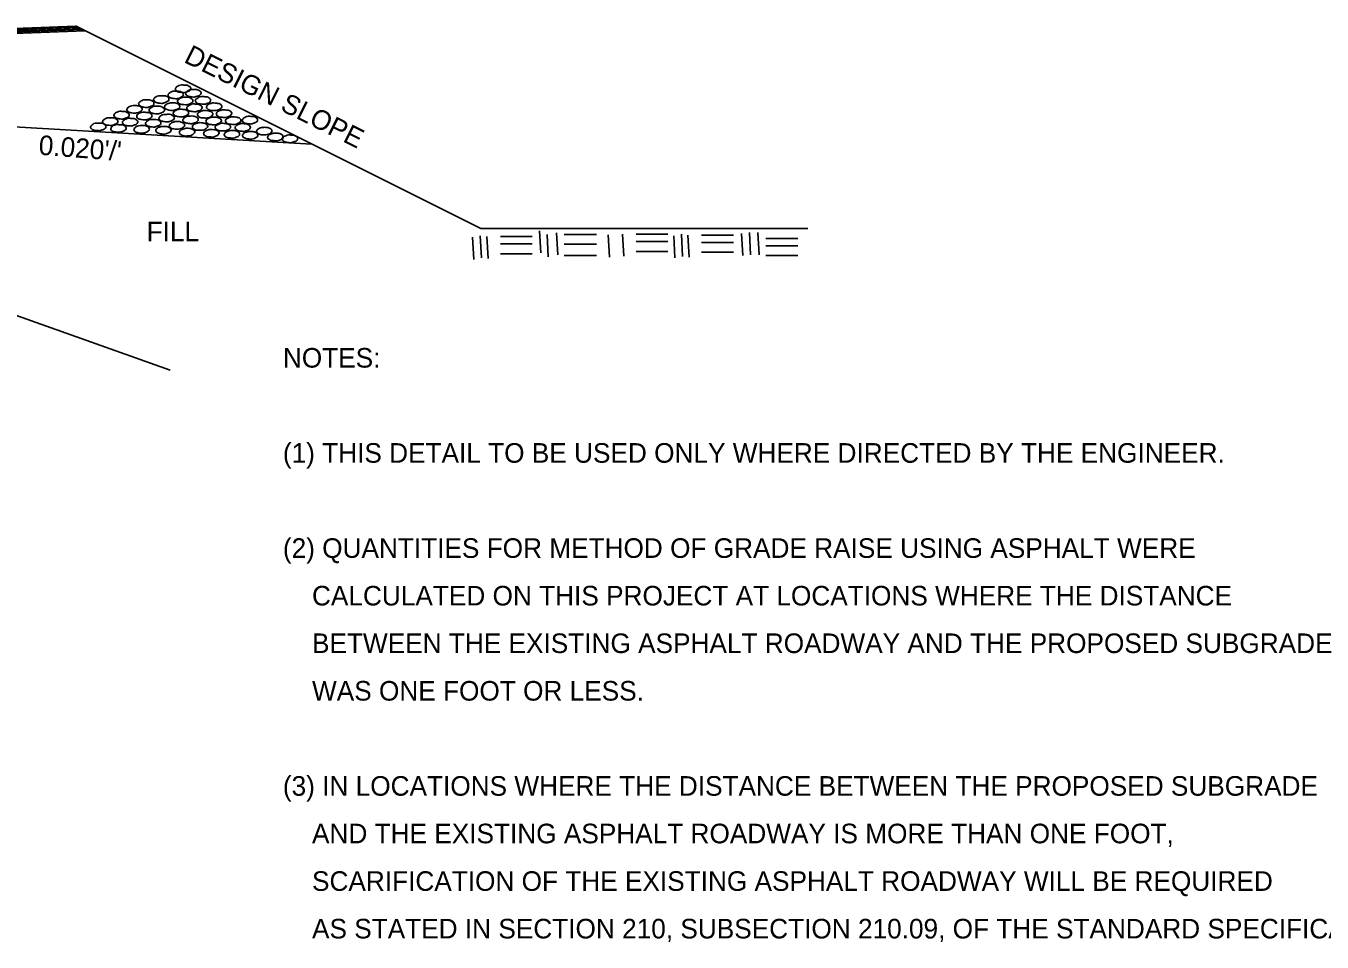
# Model space of a CAD drawing. Extents: x 3575 to 11445, y 9479 to 13278.
# Drawn here: x 5116.4 to 5513.3, y 10594.7 to 10875.3 of the extents above; entities that cross this region are included whole.
import ezdxf

# ---------------------------------------------------------------- set-up
doc = ezdxf.new("R2010")
doc.units = 0
doc.layers.add('STAMP_PE_CRAFTON-SIGNATURE', color=7, linetype='Continuous')

msp = doc.modelspace()

# ---------------------------------------------------------------- linework, layer by layer
at = {"layer": 'STAMP_PE_CRAFTON-SIGNATURE'}
for p, q in [((4487.26, 10848.04), (5134.52, 10873.86)), ((4488.11, 10848.48), (5133.79, 10874.23)), ((4488.94, 10848.88), (5133.08, 10874.59)), ((4489.79, 10849.32), (5132.33, 10874.95)), ((4490.54, 10849.68), (5131.64, 10875.29)), ((5255.72, 10813.26), (5131.53, 10875.33)), ((5050.17, 10848.13), (5203.96, 10839.12)), ((4986.73, 10831.75), (5160.57, 10769.89)), ((5355.8, 10813.26), (5255.72, 10813.26)), ((5273.69, 10812.54), (5274.04, 10805.78)), ((5253.18, 10810.59), (5253.57, 10803.82)), ((5255.51, 10811.05), (5255.9, 10804.28)), ((5257.54, 10810.83), (5257.91, 10804.06)), ((5271.47, 10810.83), (5261.68, 10810.83)), ((5271.47, 10808.57), (5261.68, 10808.57)), ((5275.98, 10811.4), (5276.35, 10804.63)), ((5278.86, 10811.99), (5279.24, 10805.21)), ((5291.1, 10811.41), (5281.27, 10811.41)), ((5291.1, 10808.51), (5281.27, 10808.51)), ((5294.72, 10811.32), (5295.12, 10804.55)), ((5299.08, 10811.57), (5299.46, 10804.8)), ((5313, 10811.57), (5303.23, 10811.57)), ((5313, 10809.31), (5303.23, 10809.31)), ((5314.76, 10811.03), (5315.15, 10804.27)), ((5317.11, 10811.51), (5317.46, 10804.73)), ((5319.12, 10811.27), (5319.5, 10804.49)), ((5333.05, 10811.27), (5323.27, 10811.27)), ((5333.05, 10809.03), (5323.27, 10809.03)), ((5335.53, 10811.75), (5335.9, 10804.99)), ((5337.96, 10812.01), (5338.33, 10805.25)), ((5340.52, 10812.01), (5340.9, 10805.25)), ((5352.81, 10810.25), (5343.02, 10810.25)), ((5271.47, 10805.56), (5261.68, 10805.56)), ((5291.1, 10805.05), (5281.27, 10805.05)), ((5313, 10806.28), (5303.23, 10806.28)), ((5333.05, 10806.01), (5323.27, 10806.01)), ((5352.81, 10808.01), (5343.02, 10808.01)), ((5352.81, 10804.97), (5343.02, 10804.97))]:
    msp.add_line(p, q, dxfattribs=at)
for points in [[(5164.52, 10854.9), (5163.68, 10855), (5162.71, 10855.25), (5162.24, 10855.74), (5162.16, 10856), (5162.41, 10856.52), (5162.64, 10856.75), (5163.21, 10857.05), (5164.01, 10857.25), (5164.43, 10857.25), (5165.06, 10857.22), (5165.75, 10857.17), (5166.27, 10856.9), (5166.8, 10856.5), (5166.88, 10856.13), (5166.73, 10855.71), (5166.34, 10855.39), (5165.96, 10855.24), (5165.4, 10855.04), (5165.06, 10854.91), (5164.52, 10854.9)], [(5167.69, 10853.54), (5166.88, 10853.65), (5165.87, 10853.88), (5165.38, 10854.38), (5165.31, 10854.63), (5165.57, 10855.16), (5165.85, 10855.36), (5166.4, 10855.68), (5167.19, 10855.9), (5167.59, 10855.9), (5168.24, 10855.83), (5168.93, 10855.8), (5169.47, 10855.53), (5169.94, 10855.12), (5170.03, 10854.77), (5169.87, 10854.37), (5169.52, 10854.02), (5169.11, 10853.86), (5168.57, 10853.67), (5168.24, 10853.57), (5167.69, 10853.54)], [(5153.28, 10850.33), (5152.46, 10850.42), (5151.46, 10850.76), (5150.99, 10851.17), (5150.9, 10851.47), (5151.16, 10851.98), (5151.44, 10852.23), (5151.96, 10852.52), (5152.75, 10852.7), (5153.19, 10852.7), (5153.81, 10852.74), (5154.5, 10852.6), (5155.05, 10852.35), (5155.54, 10851.93), (5155.61, 10851.62), (5155.49, 10851.15), (5155.09, 10850.83), (5154.74, 10850.71), (5154.14, 10850.51), (5153.81, 10850.39), (5153.28, 10850.33)], [(5157.89, 10851.62), (5157.04, 10851.71), (5156.05, 10852), (5155.54, 10852.44), (5155.49, 10852.76), (5155.74, 10853.25), (5156.02, 10853.5), (5156.56, 10853.78), (5157.37, 10853.96), (5157.79, 10853.96), (5158.42, 10853.93), (5159.12, 10853.89), (5159.62, 10853.67), (5160.11, 10853.21), (5160.19, 10852.91), (5160.03, 10852.43), (5159.65, 10852.14), (5159.28, 10851.99), (5158.75, 10851.76), (5158.42, 10851.63), (5157.89, 10851.62)], [(5162.28, 10853.03), (5161.45, 10853.13), (5160.45, 10853.4), (5159.97, 10853.86), (5159.91, 10854.15), (5160.16, 10854.64), (5160.42, 10854.88), (5160.98, 10855.19), (5161.77, 10855.39), (5162.2, 10855.39), (5162.81, 10855.32), (5163.52, 10855.28), (5164.04, 10855.08), (5164.52, 10854.61), (5164.6, 10854.33), (5164.45, 10853.84), (5164.08, 10853.57), (5163.71, 10853.37), (5163.13, 10853.15), (5162.81, 10853.05), (5162.28, 10853.03)], [(5165.23, 10851.17), (5164.36, 10851.26), (5163.38, 10851.51), (5162.88, 10852), (5162.81, 10852.27), (5163.06, 10852.79), (5163.34, 10853), (5163.9, 10853.3), (5164.7, 10853.53), (5165.12, 10853.53), (5165.75, 10853.46), (5166.44, 10853.43), (5166.95, 10853.15), (5167.45, 10852.76), (5167.53, 10852.4), (5167.37, 10851.98), (5166.98, 10851.64), (5166.63, 10851.51), (5166.09, 10851.3), (5165.75, 10851.17), (5165.23, 10851.17)], [(5170.7, 10851.34), (5169.81, 10851.43), (5168.86, 10851.64), (5168.33, 10852.16), (5168.27, 10852.41), (5168.53, 10852.94), (5168.82, 10853.15), (5169.38, 10853.48), (5170.18, 10853.68), (5170.58, 10853.68), (5171.21, 10853.65), (5171.9, 10853.6), (5172.44, 10853.33), (5172.9, 10852.92), (5172.99, 10852.58), (5172.83, 10852.14), (5172.47, 10851.81), (5172.09, 10851.64), (5171.55, 10851.47), (5171.21, 10851.35), (5170.7, 10851.34)], [(5145.69, 10846.8), (5144.85, 10846.9), (5143.88, 10847.16), (5143.41, 10847.65), (5143.33, 10847.91), (5143.57, 10848.44), (5143.8, 10848.66), (5144.37, 10848.94), (5145.18, 10849.18), (5145.59, 10849.18), (5146.2, 10849.13), (5146.91, 10849.07), (5147.43, 10848.8), (5147.96, 10848.4), (5148.03, 10848.05), (5147.89, 10847.62), (5147.49, 10847.3), (5147.14, 10847.15), (5146.56, 10846.94), (5146.2, 10846.81), (5145.69, 10846.8)], [(5149.71, 10848.6), (5148.85, 10848.69), (5147.87, 10848.96), (5147.35, 10849.4), (5147.29, 10849.7), (5147.52, 10850.2), (5147.85, 10850.44), (5148.42, 10850.79), (5149.21, 10850.94), (5149.6, 10850.94), (5150.22, 10850.91), (5150.92, 10850.83), (5151.45, 10850.63), (5151.93, 10850.16), (5151.99, 10849.88), (5151.83, 10849.39), (5151.46, 10849.11), (5151.11, 10848.92), (5150.59, 10848.75), (5150.25, 10848.66), (5149.71, 10848.6)], [(5152.7, 10846.54), (5151.83, 10846.64), (5150.87, 10846.9), (5150.39, 10847.37), (5150.32, 10847.66), (5150.57, 10848.17), (5150.81, 10848.42), (5151.39, 10848.7), (5152.17, 10848.89), (5152.59, 10848.89), (5153.23, 10848.86), (5153.92, 10848.8), (5154.44, 10848.58), (5154.95, 10848.13), (5155.02, 10847.83), (5154.86, 10847.34), (5154.5, 10847.07), (5154.11, 10846.9), (5153.55, 10846.68), (5153.23, 10846.55), (5152.7, 10846.54)], [(5156.5, 10848.38), (5155.67, 10848.48), (5154.71, 10848.75), (5154.2, 10849.23), (5154.11, 10849.47), (5154.37, 10850.03), (5154.67, 10850.25), (5155.17, 10850.58), (5155.98, 10850.76), (5156.41, 10850.76), (5157.04, 10850.78), (5157.74, 10850.66), (5158.27, 10850.39), (5158.77, 10849.99), (5158.83, 10849.67), (5158.69, 10849.21), (5158.32, 10848.87), (5157.93, 10848.71), (5157.37, 10848.55), (5157.04, 10848.44), (5156.5, 10848.38)], [(5159.53, 10845.92), (5158.69, 10846.01), (5157.72, 10846.31), (5157.22, 10846.74), (5157.14, 10847.03), (5157.4, 10847.53), (5157.69, 10847.82), (5158.2, 10848.08), (5159.01, 10848.25), (5159.42, 10848.25), (5160.04, 10848.29), (5160.74, 10848.17), (5161.28, 10847.92), (5161.78, 10847.48), (5161.86, 10847.2), (5161.71, 10846.71), (5161.33, 10846.43), (5160.95, 10846.25), (5160.39, 10846.09), (5160.04, 10845.96), (5159.53, 10845.92)], [(5161.22, 10849.42), (5160.38, 10849.52), (5159.37, 10849.82), (5158.85, 10850.25), (5158.79, 10850.56), (5159.07, 10851.04), (5159.33, 10851.3), (5159.94, 10851.6), (5160.72, 10851.79), (5161.11, 10851.79), (5161.74, 10851.76), (5162.42, 10851.68), (5162.98, 10851.48), (5163.43, 10851), (5163.52, 10850.74), (5163.36, 10850.24), (5163, 10849.98), (5162.62, 10849.78), (5162.11, 10849.6), (5161.77, 10849.48), (5161.22, 10849.42)], [(5163.88, 10847.45), (5163.05, 10847.54), (5162.07, 10847.83), (5161.58, 10848.29), (5161.52, 10848.58), (5161.77, 10849.09), (5162, 10849.31), (5162.58, 10849.6), (5163.37, 10849.82), (5163.78, 10849.82), (5164.41, 10849.78), (5165.11, 10849.72), (5165.64, 10849.45), (5166.16, 10849.04), (5166.22, 10848.71), (5166.08, 10848.25), (5165.71, 10847.96), (5165.33, 10847.82), (5164.76, 10847.58), (5164.41, 10847.47), (5163.88, 10847.45)], [(5168.02, 10849.04), (5167.18, 10849.16), (5166.19, 10849.39), (5165.71, 10849.89), (5165.63, 10850.15), (5165.88, 10850.69), (5166.17, 10850.88), (5166.73, 10851.21), (5167.52, 10851.43), (5167.93, 10851.43), (5168.55, 10851.36), (5169.25, 10851.32), (5169.77, 10851.06), (5170.28, 10850.65), (5170.35, 10850.3), (5170.2, 10849.88), (5169.81, 10849.56), (5169.45, 10849.37), (5168.88, 10849.21), (5168.55, 10849.07), (5168.02, 10849.04)], [(5171.22, 10849.44), (5172.09, 10849.35), (5173.07, 10849.09), (5173.59, 10848.61), (5173.65, 10848.33), (5173.41, 10847.84), (5173.11, 10847.6), (5172.53, 10847.28), (5171.76, 10847.1), (5171.33, 10847.1), (5170.72, 10847.15), (5170.02, 10847.18), (5169.5, 10847.41), (5169.01, 10847.87), (5168.94, 10848.17), (5169.09, 10848.63), (5169.48, 10848.92), (5169.81, 10849.11), (5170.38, 10849.31), (5170.72, 10849.4), (5171.22, 10849.44)], [(5173.99, 10851.76), (5174.81, 10851.64), (5175.8, 10851.43), (5176.33, 10850.92), (5176.4, 10850.68), (5176.16, 10850.14), (5175.87, 10849.94), (5175.28, 10849.58), (5174.5, 10849.39), (5174.09, 10849.39), (5173.48, 10849.45), (5172.76, 10849.5), (5172.23, 10849.74), (5171.77, 10850.17), (5171.71, 10850.51), (5171.86, 10850.94), (5172.19, 10851.27), (5172.56, 10851.46), (5173.11, 10851.6), (5173.46, 10851.74), (5173.99, 10851.76)], [(5177, 10849.65), (5177.85, 10849.56), (5178.83, 10849.31), (5179.36, 10848.82), (5179.42, 10848.57), (5179.17, 10848.04), (5178.89, 10847.83), (5178.3, 10847.48), (5177.54, 10847.3), (5177.1, 10847.3), (5176.47, 10847.34), (5175.75, 10847.39), (5175.26, 10847.66), (5174.77, 10848.06), (5174.71, 10848.42), (5174.87, 10848.84), (5175.22, 10849.18), (5175.58, 10849.32), (5176.15, 10849.5), (5176.46, 10849.64), (5177, 10849.65)], [(5138.52, 10843.25), (5137.69, 10843.32), (5136.73, 10843.56), (5136.25, 10844.06), (5136.16, 10844.32), (5136.43, 10844.87), (5136.67, 10845.08), (5137.23, 10845.4), (5138.04, 10845.59), (5138.43, 10845.59), (5139.08, 10845.55), (5139.78, 10845.5), (5140.32, 10845.25), (5140.79, 10844.83), (5140.88, 10844.49), (5140.72, 10844.05), (5140.38, 10843.73), (5139.95, 10843.55), (5139.41, 10843.37), (5139.08, 10843.26), (5138.52, 10843.25)], [(5142.21, 10844.87), (5141.36, 10844.92), (5140.42, 10845.21), (5139.9, 10845.67), (5139.84, 10845.96), (5140.1, 10846.47), (5140.36, 10846.7), (5140.91, 10847.01), (5141.69, 10847.2), (5142.11, 10847.2), (5142.77, 10847.17), (5143.47, 10847.13), (5143.96, 10846.87), (5144.47, 10846.44), (5144.56, 10846.12), (5144.4, 10845.66), (5144.05, 10845.37), (5143.63, 10845.19), (5143.07, 10844.96), (5142.77, 10844.87), (5142.21, 10844.87)], [(5144.77, 10842.75), (5143.9, 10842.84), (5142.92, 10843.11), (5142.44, 10843.56), (5142.35, 10843.87), (5142.65, 10844.37), (5142.86, 10844.61), (5143.47, 10844.9), (5144.24, 10845.1), (5144.64, 10845.1), (5145.28, 10845.06), (5145.97, 10845), (5146.5, 10844.78), (5147.01, 10844.32), (5147.1, 10844.02), (5146.92, 10843.54), (5146.56, 10843.27), (5146.19, 10843.09), (5145.61, 10842.87), (5145.28, 10842.77), (5144.77, 10842.75)], [(5148.3, 10844.68), (5147.45, 10844.76), (5146.5, 10845), (5146.01, 10845.5), (5145.93, 10845.76), (5146.19, 10846.29), (5146.43, 10846.5), (5147, 10846.81), (5147.81, 10847.03), (5148.19, 10847.03), (5148.83, 10846.98), (5149.52, 10846.94), (5150.06, 10846.68), (5150.57, 10846.25), (5150.65, 10845.92), (5150.49, 10845.47), (5150.11, 10845.16), (5149.74, 10844.99), (5149.2, 10844.81), (5148.83, 10844.69), (5148.3, 10844.68)], [(5151.85, 10842.46), (5151.01, 10842.56), (5150.05, 10842.82), (5149.55, 10843.3), (5149.49, 10843.55), (5149.74, 10844.1), (5149.99, 10844.3), (5150.55, 10844.63), (5151.34, 10844.83), (5151.75, 10844.83), (5152.4, 10844.79), (5153.08, 10844.74), (5153.61, 10844.48), (5154.11, 10844.06), (5154.2, 10843.72), (5154.06, 10843.28), (5153.66, 10842.95), (5153.3, 10842.81), (5152.72, 10842.61), (5152.4, 10842.47), (5151.85, 10842.46)], [(5155.46, 10844.34), (5154.59, 10844.44), (5153.59, 10844.74), (5153.08, 10845.17), (5152.99, 10845.47), (5153.27, 10845.97), (5153.55, 10846.21), (5154.12, 10846.52), (5154.91, 10846.71), (5155.33, 10846.71), (5155.94, 10846.69), (5156.65, 10846.61), (5157.18, 10846.39), (5157.65, 10845.93), (5157.74, 10845.63), (5157.57, 10845.16), (5157.19, 10844.87), (5156.83, 10844.7), (5156.31, 10844.53), (5155.97, 10844.4), (5155.46, 10844.34)], [(5158.49, 10844.55), (5159.29, 10844.53), (5160.3, 10844.18), (5160.8, 10843.72), (5160.88, 10843.44), (5160.63, 10842.91), (5160.31, 10842.71), (5159.79, 10842.44), (5158.96, 10842.21), (5158.55, 10842.18), (5157.93, 10842.23), (5157.25, 10842.37), (5156.73, 10842.58), (5156.24, 10842.95), (5156.17, 10843.3), (5156.31, 10843.73), (5156.69, 10844.05), (5157.04, 10844.27), (5157.59, 10844.44), (5157.95, 10844.53), (5158.49, 10844.55)], [(5162.62, 10846.04), (5163.45, 10846.01), (5164.45, 10845.67), (5164.95, 10845.21), (5165.02, 10844.91), (5164.76, 10844.4), (5164.46, 10844.18), (5163.92, 10843.93), (5163.09, 10843.7), (5162.69, 10843.66), (5162.07, 10843.73), (5161.4, 10843.85), (5160.86, 10844.06), (5160.38, 10844.44), (5160.3, 10844.78), (5160.45, 10845.22), (5160.83, 10845.52), (5161.18, 10845.76), (5161.74, 10845.93), (5162.09, 10846.01), (5162.62, 10846.04)], [(5165.71, 10844.02), (5166.53, 10843.92), (5167.52, 10843.58), (5168.01, 10843.17), (5168.09, 10842.87), (5167.82, 10842.38), (5167.53, 10842.12), (5166.98, 10841.81), (5166.19, 10841.62), (5165.78, 10841.62), (5165.16, 10841.61), (5164.46, 10841.72), (5163.92, 10841.98), (5163.43, 10842.41), (5163.36, 10842.7), (5163.52, 10843.18), (5163.88, 10843.48), (5164.27, 10843.64), (5164.83, 10843.83), (5165.16, 10843.94), (5165.71, 10844.02)], [(5166.78, 10847.74), (5167.59, 10847.72), (5168.63, 10847.36), (5169.1, 10846.9), (5169.18, 10846.61), (5168.91, 10846.12), (5168.64, 10845.88), (5168.09, 10845.63), (5167.28, 10845.42), (5166.86, 10845.38), (5166.23, 10845.45), (5165.57, 10845.55), (5165.03, 10845.73), (5164.53, 10846.15), (5164.46, 10846.45), (5164.61, 10846.92), (5165, 10847.22), (5165.35, 10847.47), (5165.89, 10847.65), (5166.24, 10847.72), (5166.78, 10847.74)], [(5169.66, 10845.7), (5170.49, 10845.63), (5171.5, 10845.33), (5172.01, 10844.88), (5172.09, 10844.61), (5171.83, 10844.1), (5171.55, 10843.87), (5170.97, 10843.5), (5170.2, 10843.37), (5169.77, 10843.37), (5169.13, 10843.39), (5168.45, 10843.45), (5167.93, 10843.69), (5167.45, 10844.14), (5167.37, 10844.44), (5167.53, 10844.9), (5167.91, 10845.21), (5168.27, 10845.38), (5168.8, 10845.55), (5169.12, 10845.66), (5169.66, 10845.7)], [(5173.81, 10847.41), (5174.66, 10847.34), (5175.66, 10847.06), (5176.2, 10846.56), (5176.26, 10846.29), (5175.99, 10845.77), (5175.7, 10845.57), (5175.11, 10845.3), (5174.31, 10845.03), (5173.89, 10845.03), (5173.27, 10845.1), (5172.59, 10845.17), (5172.08, 10845.4), (5171.61, 10845.81), (5171.53, 10846.14), (5171.69, 10846.58), (5172.02, 10846.9), (5172.37, 10847.1), (5172.92, 10847.3), (5173.28, 10847.37), (5173.81, 10847.41)], [(5176.68, 10845.5), (5177.54, 10845.43), (5178.52, 10845.15), (5179, 10844.69), (5179.08, 10844.4), (5178.83, 10843.9), (5178.53, 10843.64), (5177.98, 10843.37), (5177.19, 10843.16), (5176.8, 10843.16), (5176.16, 10843.22), (5175.47, 10843.26), (5174.94, 10843.5), (5174.42, 10843.93), (5174.36, 10844.22), (5174.51, 10844.7), (5174.91, 10844.99), (5175.27, 10845.16), (5175.8, 10845.4), (5176.16, 10845.5), (5176.68, 10845.5)], [(5179.84, 10847.48), (5180.68, 10847.39), (5181.66, 10847.14), (5182.17, 10846.67), (5182.25, 10846.39), (5181.96, 10845.87), (5181.68, 10845.66), (5181.13, 10845.35), (5180.33, 10845.12), (5179.92, 10845.12), (5179.29, 10845.19), (5178.61, 10845.24), (5178.07, 10845.47), (5177.59, 10845.92), (5177.54, 10846.22), (5177.65, 10846.68), (5178.04, 10846.98), (5178.4, 10847.16), (5178.95, 10847.39), (5179.33, 10847.47), (5179.84, 10847.48)], [(5182.79, 10845.41), (5183.61, 10845.35), (5184.63, 10845.03), (5185.09, 10844.57), (5185.17, 10844.27), (5184.92, 10843.77), (5184.68, 10843.52), (5184.1, 10843.3), (5183.31, 10843.04), (5182.9, 10843.04), (5182.25, 10843.09), (5181.58, 10843.2), (5181.04, 10843.39), (5180.55, 10843.81), (5180.45, 10844.15), (5180.63, 10844.6), (5180.99, 10844.9), (5181.39, 10845.09), (5181.91, 10845.31), (5182.25, 10845.4), (5182.79, 10845.41)], [(5185, 10845.3), (5184.17, 10845.4), (5183.19, 10845.66), (5182.71, 10846.13), (5182.63, 10846.41), (5182.9, 10846.92), (5183.14, 10847.15), (5183.71, 10847.44), (5184.48, 10847.66), (5184.92, 10847.66), (5185.55, 10847.62), (5186.24, 10847.56), (5186.76, 10847.3), (5187.27, 10846.88), (5187.34, 10846.54), (5187.2, 10846.1), (5186.83, 10845.79), (5186.44, 10845.65), (5185.86, 10845.43), (5185.55, 10845.31), (5185, 10845.3)], [(5189.37, 10844.28), (5190.21, 10844.22), (5191.19, 10843.92), (5191.69, 10843.5), (5191.76, 10843.25), (5191.5, 10842.69), (5191.25, 10842.41), (5190.65, 10842.16), (5189.88, 10841.99), (5189.48, 10841.96), (5188.85, 10841.96), (5188.13, 10842.07), (5187.64, 10842.32), (5187.12, 10842.71), (5187.04, 10843.04), (5187.19, 10843.5), (5187.58, 10843.85), (5187.94, 10844.02), (5188.51, 10844.18), (5188.84, 10844.22), (5189.37, 10844.28)], [(5173.16, 10843.64), (5174, 10843.54), (5174.98, 10843.3), (5175.47, 10842.82), (5175.54, 10842.54), (5175.27, 10842.04), (5175.02, 10841.81), (5174.43, 10841.52), (5173.65, 10841.29), (5173.25, 10841.29), (5172.64, 10841.33), (5171.93, 10841.4), (5171.4, 10841.62), (5170.89, 10842.07), (5170.82, 10842.38), (5170.97, 10842.84), (5171.34, 10843.15), (5171.73, 10843.32), (5172.29, 10843.5), (5172.64, 10843.61), (5173.16, 10843.64)], [(5179.47, 10843.32), (5180.33, 10843.27), (5181.29, 10842.94), (5181.77, 10842.48), (5181.85, 10842.18), (5181.59, 10841.69), (5181.36, 10841.48), (5180.79, 10841.21), (5180, 10840.93), (5179.58, 10840.93), (5178.95, 10841.01), (5178.28, 10841.09), (5177.72, 10841.29), (5177.2, 10841.72), (5177.12, 10842.05), (5177.29, 10842.5), (5177.65, 10842.81), (5178.04, 10843.01), (5178.61, 10843.23), (5178.95, 10843.3), (5179.47, 10843.32)], [(5185.08, 10842.99), (5185.89, 10842.96), (5186.9, 10842.66), (5187.35, 10842.2), (5187.44, 10841.95), (5187.19, 10841.39), (5186.94, 10841.17), (5186.39, 10840.87), (5185.58, 10840.68), (5185.13, 10840.64), (5184.53, 10840.72), (5183.85, 10840.84), (5183.3, 10841.01), (5182.8, 10841.43), (5182.72, 10841.72), (5182.89, 10842.18), (5183.24, 10842.53), (5183.62, 10842.75), (5184.2, 10842.88), (5184.54, 10842.96), (5185.08, 10842.99)], [(5192.76, 10842.53), (5193.6, 10842.44), (5194.57, 10842.14), (5195.03, 10841.69), (5195.12, 10841.43), (5194.89, 10840.88), (5194.62, 10840.64), (5194.04, 10840.34), (5193.25, 10840.17), (5192.84, 10840.17), (5192.21, 10840.19), (5191.54, 10840.25), (5191, 10840.51), (5190.48, 10840.91), (5190.4, 10841.27), (5190.55, 10841.7), (5190.94, 10842.03), (5191.3, 10842.18), (5191.87, 10842.37), (5192.24, 10842.47), (5192.76, 10842.53)], [(5197.32, 10839.57), (5196.45, 10839.64), (5195.48, 10839.91), (5194.99, 10840.38), (5194.93, 10840.67), (5195.2, 10841.2), (5195.42, 10841.41), (5196.01, 10841.69), (5196.81, 10841.94), (5197.22, 10841.94), (5197.83, 10841.89), (5198.53, 10841.82), (5199.05, 10841.57), (5199.56, 10841.15), (5199.62, 10840.84), (5199.5, 10840.35), (5199.13, 10840.07), (5198.76, 10839.89), (5198.17, 10839.68), (5197.83, 10839.58), (5197.32, 10839.57)]]:
    msp.add_spline(points, degree=3, dxfattribs=at)

# ---------------------------------------------------------------- texts
for s, rotation, p in [('DESIGN SLOPE', 333.435, (5164.47, 10864.37)), ("0.020'/'", 355.6232, (5120.15, 10835.9))]:
    msp.add_text(s, height=6, rotation=rotation, dxfattribs=at).set_placement(p)
for s, p in [('FILL', (5153.36, 10809.35)), ('NOTES:', (5195.09, 10770.67)), ('(1) THIS DETAIL TO BE USED ONLY WHERE DIRECTED BY THE ENGINEER.', (5195.09, 10741.53)), ('(2) QUANTITIES FOR METHOD OF GRADE RAISE USING ASPHALT WERE', (5195.09, 10712.39)), ('    CALCULATED ON THIS PROJECT AT LOCATIONS WHERE THE DISTANCE', (5195.09, 10697.81)), ('    BETWEEN THE EXISTING ASPHALT ROADWAY AND THE PROPOSED SUBGRADE', (5195.09, 10683.24)), ('    WAS ONE FOOT OR LESS.', (5195.09, 10668.67)), ('(3) IN LOCATIONS WHERE THE DISTANCE BETWEEN THE PROPOSED SUBGRADE', (5195.09, 10639.53)), ('    AND THE EXISTING ASPHALT ROADWAY IS MORE THAN ONE FOOT,', (5195.09, 10624.96)), ('    SCARIFICATION OF THE EXISTING ASPHALT ROADWAY WILL BE REQUIRED', (5195.09, 10610.39)), ('    AS STATED IN SECTION 210, SUBSECTION 210.09, OF THE STANDARD SPECIFICATIONS.', (5195.09, 10595.81))]:
    msp.add_text(s, height=6, dxfattribs=at).set_placement(p)

doc.saveas('drawing.dxf')
